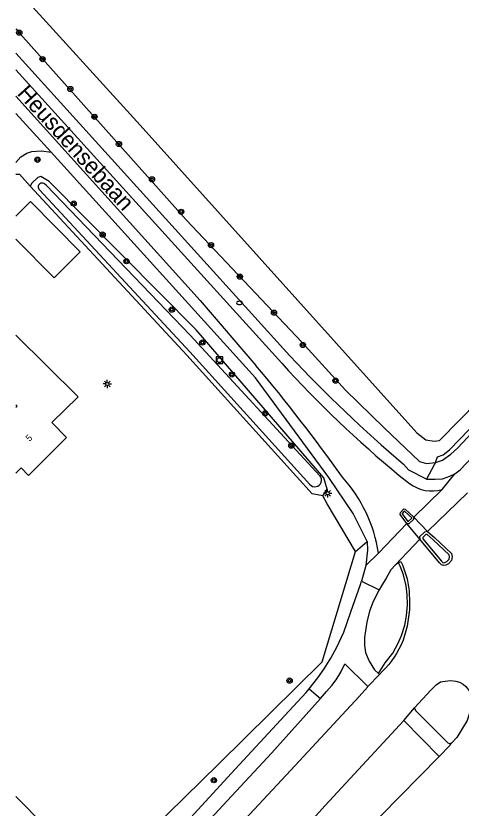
# Model space of a CAD drawing. Extents: x 141000 to 143000, y 400580 to 403500.
# Drawn here: x 141000 to 141068, y 401460.8 to 401581.9 of the extents above; entities that cross this region are included whole.
import ezdxf

# ---------------------------------------------------------------- set-up
doc = ezdxf.new("R2010")
doc.units = 0
for name, color, linetype in [('gg-afsc-erfafscheiding', 7, 'Continuous'), ('gg-afsc-hekwerk', 7, 'Continuous'), ('gg-afsc-muur', 7, 'Continuous'), ('gg-anno-huisnummerreeks BGT', 7, 'Continuous'), ('gg-anno-openbare ruimte label', 7, 'Continuous'), ('gg-bbg-bijgebouw', 7, 'Continuous'), ('gg-bbg-hoofdgebouw', 7, 'Continuous'), ('gg-knt-verharding', 7, 'Continuous'), ('gg-knt-verharding nz', 7, 'Continuous'), ('gg-kntw-bovenkant insteek waterloop', 7, 'Continuous'), ('gg-kntw-waterlijn', 7, 'Continuous'), ('gt-grn-groengrens', 7, 'Continuous'), ('gt-grn-groengrens NZ', 7, 'Continuous'), ('gt-grn-vlakafsluiter', 7, 'Continuous'), ('gt-grn-weggrens', 7, 'Continuous'), ('gt-symb-boom', 7, 'Continuous'), ('gt-symb-brandkraan', 7, 'Continuous'), ('gt-symb-lichtmast', 7, 'Continuous'), ('gt-symb-rioolschacht', 7, 'Continuous'), ('gx-grn-maaiveld', 7, 'Continuous')]:
    doc.layers.add(name, color=color, linetype=linetype)

# ---------------------------------------------------------------- blocks, each defined once
blk = doc.blocks.new('gt0-BOOM')
at = {"layer": 'gt-symb-boom'}
for radius in [0.4, 0.2]:
    blk.add_circle((0, 0), radius, dxfattribs=at)
blk = doc.blocks.new('gt0-BR')
at = {"layer": 'gt-symb-brandkraan'}
for centre, radius, start, end in [((-0.24, 0), 0.206, 107.5669, 252.4331), ((0.6, -2.66), 3, 106.892, 107.5669), ((0, -0.69), 0.938, 73.108, 106.892), ((-0.6, -2.66), 3, 72.4331, 73.108), ((0.24, 0), 0.206, 287.567, 72.4331), ((0.6, 2.66), 3, 252.4331, 253.108), ((0, 0.69), 0.938, 253.108, 286.8921), ((-0.6, 2.66), 3, 286.8921, 287.567)]:
    blk.add_arc(centre, radius, start, end, dxfattribs=at)
blk = doc.blocks.new('gt0-LMAST')
at = {"layer": 'gt-symb-lichtmast'}
for p, q in [((-0.18, 0.17), (-0.45, 0.44)), ((-0.01, 0.25), (-0.01, 0.62)), ((0.17, 0.17), (0.44, 0.44)), ((-0.26, 0), (-0.63, 0)), ((-0.18, -0.18), (-0.45, -0.45)), ((-0.01, -0.25), (-0.01, -0.63)), ((0.44, -0.45), (0.17, -0.18)), ((0.24, 0), (0.62, 0))]:
    blk.add_line(p, q, dxfattribs=at)
blk.add_circle((-0.01, 0), 0.25, dxfattribs=at)
blk = doc.blocks.new('gt0-RS')
at = {"layer": 'gt-symb-rioolschacht'}
blk.add_lwpolyline([(-0.5, -0.5), (0.5, -0.5), (0.5, 0.5), (-0.5, 0.5)], close=True, dxfattribs=at)
blk.add_circle((0, 0), 0.375, dxfattribs=at)

msp = doc.modelspace()

# ---------------------------------------------------------------- linework, layer by layer
at = {"layer": 'gg-afsc-erfafscheiding'}
msp.add_lwpolyline([(141051.86, 401500.01), (141047.53, 401507.31), (141046.88, 401508.54)], dxfattribs=at)
at = {"layer": 'gg-afsc-hekwerk'}
msp.add_lwpolyline([(141000, 401557.7), (141000.56, 401557.72), (141002.18, 401555.85)], dxfattribs=at)
at = {"layer": 'gg-afsc-muur'}
msp.add_line((141051.86, 401500.01), (141047.53, 401507.31), dxfattribs=at)
msp.add_lwpolyline([(141012.72, 401449.64), (141030.97, 401467.56), (141046.78, 401483.15), (141051.86, 401500.01)], dxfattribs=at)
at = {"layer": 'gg-bbg-bijgebouw'}
msp.add_lwpolyline([(141000, 401547.77), (141005.84, 401541.85), (141009.81, 401545.82), (141002.22, 401553.51), (141000, 401551.29)], dxfattribs=at)
at = {"layer": 'gg-bbg-hoofdgebouw'}
for points in [[(141000, 401512.01), (141000.81, 401512.8), (141001.93, 401511.67), (141007.74, 401517.45), (141005.49, 401519.72), (141009.49, 401523.65), (141000, 401533.09)], [(141000, 401522.42), (141000.18, 401522.24), (141000, 401522.06)]]:
    msp.add_lwpolyline(points, dxfattribs=at)
at = {"layer": 'gg-knt-verharding'}
for p, q in [((141000, 401576.19), (141041.85, 401529.92)), ((141000, 401566.98), (141005.38, 401561.04)), ((141005.38, 401561.04), (141036.57, 401526.59)), ((141059.2, 401513.36), (141060.01, 401512.44)), ((141062.69, 401511.08), (141060.01, 401512.44)), ((141062.87, 401503.07), (141060.79, 401505.28)), ((141061.7, 401501.93), (141059.71, 401504.29)), ((141053.46, 401497.9), (141052.8, 401495.5)), ((141052.8, 401495.5), (141055.5, 401494.17)), ((141059.22, 401474.2), (141060.85, 401476.15)), ((141064.64, 401468.71), (141059.22, 401474.2))]:
    msp.add_line(p, q, dxfattribs=at)
for points in [[(141000, 401559.49), (141000.78, 401560.33), (141001.68, 401560.88), (141002.43, 401561.14), (141003.93, 401561.28), (141005.38, 401561.04)], [(141053.64, 401501.56), (141053.01, 401502.79), (141051.48, 401505.82), (141047.77, 401511.33), (141036.57, 401526.59)], [(141067.02, 401511.89), (141067.86, 401512.52), (141069.66, 401514.47)], [(141062.69, 401511.08), (141064.03, 401511.07), (141065.15, 401511.15), (141066.29, 401511.52), (141067.02, 401511.89)], [(141059.71, 401504.29), (141058.7, 401505.69), (141058.71, 401505.98), (141059.24, 401506.54), (141059.46, 401506.52), (141060.79, 401505.28)], [(141059.71, 401504.29), (141060.05, 401504.33), (141060.76, 401504.99), (141060.79, 401505.28)], [(141062.87, 401503.07), (141062.4, 401502.98), (141061.64, 401502.27), (141061.7, 401501.93)], [(141062.87, 401503.07), (141063.96, 401502.12), (141066.52, 401499.72), (141066.64, 401499.23), (141066.5, 401498.68), (141066.08, 401498.17), (141065.63, 401497.95), (141065.29, 401497.89), (141064.97, 401497.99), (141064.71, 401498.29), (141061.7, 401501.93)], [(141053.64, 401501.56), (141053.7, 401500.22), (141053.46, 401497.9)], [(141057.26, 401497.23), (141056.55, 401495.97), (141055.85, 401494.8), (141055.5, 401494.17)], [(141044.8, 401479.06), (141046.09, 401480.71), (141047.06, 401482.11), (141048.07, 401483.71), (141049.01, 401485.42), (141050.08, 401487.69), (141051.17, 401490.81), (141052.65, 401494.97), (141052.8, 401495.5)], [(141055.5, 401494.17), (141055.08, 401493.42), (141054.52, 401492.25), (141054.01, 401490.93), (141053.57, 401489.25), (141053.39, 401487.89), (141053.23, 401486.9), (141053.24, 401485.68), (141053.41, 401484.62), (141053.96, 401483.29), (141054.78, 401481.96), (141055.35, 401481.4)], [(141046.51, 401477.57), (141047.44, 401478.62), (141048.23, 401479.54), (141048.89, 401480.44), (141049.61, 401481.58), (141050.23, 401482.88), (141053.72, 401479.41)], [(141000, 401430.85), (141007.46, 401438.67), (141014.48, 401446.26), (141025.57, 401458.1), (141033.5, 401466.78), (141041.09, 401474.96), (141044.35, 401478.47), (141044.8, 401479.06)], [(141000, 401427.46), (141004.73, 401432.5), (141015.52, 401444.01), (141026.69, 401455.86), (141031.59, 401461.2), (141039.1, 401469.24), (141046.51, 401477.57)], [(141060.85, 401476.15), (141060.9, 401475.89), (141061.06, 401475.7), (141065.96, 401470.81), (141066.27, 401470.68), (141066.57, 401470.77)], [(141064.64, 401468.71), (141066.34, 401470.44), (141066.3, 401470.49), (141066.57, 401470.77)]]:
    msp.add_lwpolyline(points, dxfattribs=at)
msp.add_arc((141202.85, 401681.15), 220.89, 223.2073, 229.4315, dxfattribs=at)
at = {"layer": 'gg-knt-verharding nz'}
for p, q in [((141000, 401573.63), (141040.61, 401528.79)), ((141058.54, 401511.66), (141060.13, 401510.43)), ((141065.09, 401509.51), (141060.79, 401505.28)), ((141068.96, 401509.02), (141062.87, 401503.07)), ((141055.35, 401499.79), (141059.71, 401504.29)), ((141057.98, 401497.99), (141061.7, 401501.93)), ((141057.26, 401497.23), (141057.98, 401497.99))]:
    msp.add_line(p, q, dxfattribs=at)
msp.add_lwpolyline([(141000, 401569.6), (141028.16, 401538.39), (141036.64, 401528.47)], dxfattribs=at)
for centre, radius, start, end in [((140842.92, 401364.86), 253.57, 35.3042, 40.1816), ((141170.02, 401646.28), 174.79, 222.2343, 230.3701), ((141033.59, 401496.6), 21.99, 8.319, 42.3025), ((141063.49, 401514.75), 5.47, 232.0593, 286.9776)]:
    msp.add_arc(centre, radius, start, end, dxfattribs=at)
at = {"layer": 'gg-kntw-bovenkant insteek waterloop'}
for points in [[(141000, 401586.12), (141018.96, 401565.19), (141061.21, 401518.18), (141062.62, 401517.11), (141063.89, 401516.89), (141064.68, 401516.97), (141076.53, 401529.07), (141105.54, 401559.57), (141144.61, 401599.33), (141175.72, 401631.37), (141182.02, 401638.25), (141183.23, 401640.29)], [(141000, 401579.92), (141000.68, 401579.15), (141026.03, 401550.72), (141043.69, 401532), (141050.34, 401524.67), (141056.24, 401518.95), (141061.61, 401513.8), (141062.71, 401513.46), (141064.07, 401513.61)], [(141046.88, 401508.54), (141047.51, 401509.56), (141047.02, 401511.3), (141027.51, 401533.92), (141005.07, 401556.56), (141003.79, 401557.33), (141003.37, 401557.2), (141002.44, 401556.31), (141002.18, 401555.85)], [(141046.88, 401508.54), (141045.27, 401508.85), (141026.09, 401530.06), (141002.18, 401555.85)], [(141064.07, 401513.61), (141064.4, 401514.49), (141065.23, 401514.81), (141066.24, 401515.55), (141081.09, 401530.97), (141087.31, 401537.61)], [(141000, 401462.61), (141008.71, 401453.79), (141011.95, 401450.51), (141012.72, 401449.64)]]:
    msp.add_lwpolyline(points, dxfattribs=at)
at = {"layer": 'gg-kntw-waterlijn'}
for points in [[(141046.4, 401511.62), (141026.63, 401533.07), (141004.65, 401556.02), (141004.41, 401556.17)], [(141044.88, 401510.29), (141026.59, 401530.52), (141003.62, 401555.3)]]:
    msp.add_lwpolyline(points, dxfattribs=at)
for centre, radius, start, end in [((141004, 401555.74), 0.589, 46.3445, 229.095), ((141045.66, 401510.94), 1.01, 219.9139, 42.3671)]:
    msp.add_arc(centre, radius, start, end, dxfattribs=at)
at = {"layer": 'gt-grn-groengrens'}
msp.add_lwpolyline([(141064.07, 401513.61), (141065.16, 401514.01), (141066.41, 401514.91), (141067.48, 401515.85), (141087.57, 401537.37)], dxfattribs=at)
at = {"layer": 'gt-grn-groengrens NZ'}
msp.add_lwpolyline([(141064.07, 401513.61), (141063.89, 401513.29), (141062.69, 401511.08)], dxfattribs=at)
at = {"layer": 'gt-grn-vlakafsluiter'}
msp.add_line((141051.86, 401500.01), (141053.64, 401501.56), dxfattribs=at)
at = {"layer": 'gt-grn-weggrens'}
for p, q in [((141065.09, 401509.51), (141067.02, 401511.89)), ((141055.35, 401499.79), (141053.46, 401497.9)), ((141044.8, 401479.06), (141046.51, 401477.57))]:
    msp.add_line(p, q, dxfattribs=at)
at = {"layer": 'gx-grn-maaiveld'}
for p, q in [((141058.45, 401498.29), (141057.98, 401497.99)), ((141053.72, 401479.41), (141055.52, 401481.26)), ((141055.35, 401481.4), (141055.52, 401481.26))]:
    msp.add_line(p, q, dxfattribs=at)
for points in [[(141059, 401505.78), (141059.85, 401504.61), (141059.91, 401504.61), (141060.47, 401505.13), (141060.48, 401505.19), (141059.42, 401506.16), (141059.3, 401506.17), (141059.01, 401505.86), (141059, 401505.78)], [(141062.15, 401501.98), (141065.01, 401498.55), (141065.19, 401498.34), (141065.31, 401498.3), (141065.51, 401498.34), (141065.82, 401498.49), (141066.14, 401498.87), (141066.23, 401499.23), (141066.16, 401499.51), (141063.7, 401501.82), (141062.78, 401502.64), (141062.59, 401502.61), (141062.14, 401502.18), (141062.15, 401501.98)], [(141012.72, 401449.64), (141030.97, 401467.56), (141046.78, 401483.15), (141051.86, 401500.01)], [(141055.35, 401481.4), (141056.39, 401483.01), (141057.56, 401484.52), (141058.4, 401486.01), (141058.91, 401487.2), (141059.39, 401488.78), (141059.64, 401490.2), (141059.8, 401491.87), (141059.77, 401493.41), (141059.59, 401494.8), (141059.2, 401496.48), (141058.69, 401497.81), (141058.45, 401498.29)], [(141058.45, 401498.29), (141058.8, 401498.48), (141059.04, 401497.97), (141059.74, 401495.85), (141060.06, 401494.02), (141060.13, 401492.17), (141060.12, 401491.11), (141059.74, 401488.62), (141059.14, 401486.49), (141058.83, 401485.79), (141058.49, 401485.11), (141058.11, 401484.44), (141057.85, 401484.02), (141057.41, 401483.39), (141056.95, 401482.78), (141056.45, 401482.2), (141055.95, 401481.67), (141055.52, 401481.26)], [(141060.85, 401476.15), (141063.39, 401478.83), (141064.17, 401479.65), (141064.86, 401480.09), (141065.54, 401480.22), (141066.37, 401480.33), (141067.2, 401480.24), (141067.76, 401480.06), (141068.28, 401479.77), (141068.73, 401479.39), (141069.25, 401478.68), (141069.54, 401477.87), (141069.71, 401476.8), (141068.9, 401474.18), (141067.35, 401471.61), (141066.57, 401470.77)], [(141000, 401421.47), (141011.04, 401433.15), (141016.49, 401439.03), (141024.49, 401447.64), (141032.87, 401456.81), (141041.98, 401466.59), (141052.41, 401477.86), (141053.69, 401479.29), (141053.72, 401479.41)], [(141000, 401410.72), (141016.78, 401428.44), (141021.71, 401433.72), (141029.6, 401442.09), (141038.41, 401451.49), (141047.23, 401461.19), (141059.22, 401474.2)], [(141000, 401404.06), (141010.08, 401414.03), (141032.6, 401436.34), (141052.74, 401456.56), (141064.64, 401468.71)]]:
    msp.add_lwpolyline(points, dxfattribs=at)

# ---------------------------------------------------------------- block references
at = {"layer": 'gt-symb-boom'}
for p in [(141000.52, 401579.32), (141004.08, 401575.28), (141008.32, 401570.7), (141012, 401566.47), (141015.74, 401562.3), (141003.3, 401559.9), (141020.79, 401556.9), (141008.83, 401553.2), (141025.24, 401551.95), (141013.25, 401548.46), (141029.8, 401546.85), (141016.89, 401544.39), (141034.2, 401542.04), (141023.83, 401537), (141039.42, 401536.53), (141028.48, 401531.96), (141043.82, 401531.59), (141033, 401527.09), (141048.82, 401526.15), (141038.08, 401521.15), (141042.06, 401516.2), (141041.8, 401480.3), (141030.24, 401465.08)]:
    msp.add_blockref('gt0-BOOM', p, dxfattribs=at)
at = {"layer": 'gt-symb-brandkraan'}
msp.add_blockref('gt0-BR', (141034.15, 401538.02), dxfattribs=at)
at = {"layer": 'gt-symb-lichtmast'}
for p in [(141013.96, 401525.63), (141047.61, 401508.93)]:
    msp.add_blockref('gt0-LMAST', p, dxfattribs=at)
at = {"layer": 'gt-symb-rioolschacht'}
msp.add_blockref('gt0-RS', (141031.1, 401529.27), dxfattribs=at)

# ---------------------------------------------------------------- texts
at = {"layer": 'gg-anno-huisnummerreeks BGT'}
msp.add_text('5', height=1, rotation=44.9, dxfattribs=at).set_placement((141002.09, 401516.77))
at = {"layer": 'gg-anno-openbare ruimte label'}
msp.add_text('Heusdensebaan', height=2.5, rotation=312.2, dxfattribs=at).set_placement((141000.07, 401569.94))

doc.saveas('drawing.dxf')
